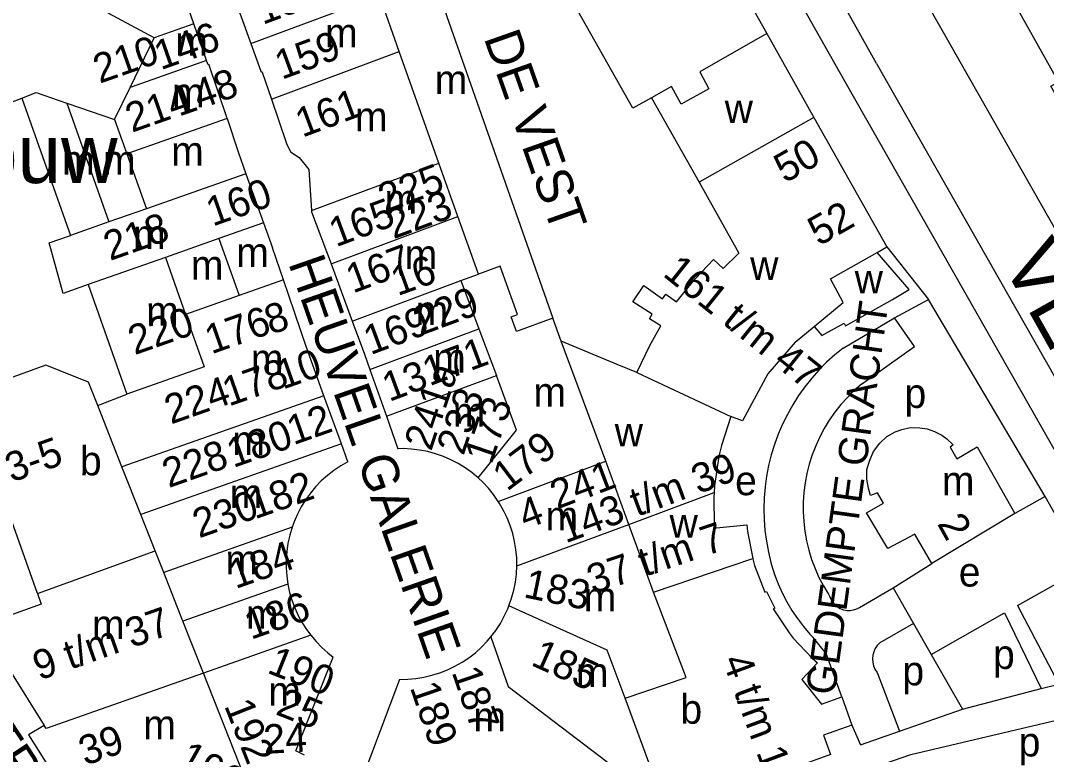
# Model space of a CAD drawing. Extents: x 160673 to 161924, y 382258 to 384145.
# Drawn here: x 161438.3 to 161578.5, y 383227.2 to 383327.4 of the extents above; entities that cross this region are included whole.
import ezdxf

# ---------------------------------------------------------------- set-up
doc = ezdxf.new("R2010")
doc.units = 0
for name, color, linetype in [('BLT_Basislijn', 7, 'Continuous'), ('BLT_Bebouwing', 7, 'Continuous'), ('BLT_Bebouwing_beschrifting', 7, 'Continuous'), ('BLT_Centroide', 7, 'Continuous'), ('BLT_Huisnummer', 7, 'Continuous'), ('BLT_Huisnummer_reeks', 7, 'Continuous'), ('BLT_Onderverdeling_panden', 7, 'Continuous'), ('BLT_Straatnaam', 7, 'Continuous'), ('BLT_Straatnaam_hoofdweg', 7, 'Continuous'), ('BLT_Straatnaam_verkleind', 7, 'Continuous'), ('BLT_Vlakafsluiter', 7, 'Continuous')]:
    doc.layers.add(name, color=color, linetype=linetype)

msp = doc.modelspace()

# ---------------------------------------------------------------- linework, layer by layer
at = {"layer": 'BLT_Basislijn'}
for p, q in [((161557.77, 383286.8), (161562.38, 383289.3)), ((161550.74, 383282.66), (161557.77, 383286.8)), ((161578.34, 383262.37), (161574.21, 383260.08)), ((161557.57, 383249.93), (161562.84, 383253.26)), ((161574.56, 383247.5), (161583.82, 383252.74)), ((161574.56, 383247.5), (161580.19, 383236.75)), ((161560.34, 383245.03), (161562.75, 383240.8)), ((161562.75, 383240.8), (161567.02, 383233.34)), ((161555.37, 383238.36), (161558.42, 383230.33)), ((161567.02, 383233.34), (161577.8, 383236.18)), ((161577.8, 383236.18), (161580.19, 383236.75))]:
    msp.add_line(p, q, dxfattribs=at)
for points in [[(161519.25, 383375.41), (161519.91, 383374.2), (161546.88, 383326.32), (161546.88, 383326.31)], [(161551.92, 383347.93), (161559.95, 383333.68), (161564.02, 383326.44), (161607.72, 383249.64), (161611.72, 383242.87)], [(161555.31, 383321.52), (161599.03, 383244.7), (161601.19, 383240.41)], [(161550.95, 383319.07), (161550.96, 383319.06), (161595.67, 383240.5)], [(161556.69, 383296.47), (161562.38, 383289.3)], [(161578.34, 383262.37), (161562.38, 383289.3)], [(161553.24, 383277.73), (161560.48, 383282.86), (161557.77, 383286.8)], [(161550.74, 383282.66), (161549.58, 383281.72), (161548.48, 383280.72), (161547.43, 383279.66), (161546.44, 383278.55), (161545.51, 383277.39), (161544.64, 383276.17), (161543.84, 383274.91), (161543.11, 383273.61), (161542.45, 383272.28), (161541.86, 383270.91), (161541.35, 383269.51), (161540.91, 383268.09), (161540.55, 383266.64), (161540.27, 383265.18), (161540.07, 383263.7), (161539.94, 383262.22), (161539.9, 383260.73), (161539.94, 383259.24), (161540.05, 383257.75), (161540.25, 383256.27), (161540.52, 383254.81), (161540.87, 383253.36), (161540.96, 383253.04)], [(161553.24, 383277.73), (161552.25, 383276.85), (161551.31, 383275.92), (161550.42, 383274.94), (161549.6, 383273.9), (161548.84, 383272.82), (161548.15, 383271.69), (161547.53, 383270.52), (161546.98, 383269.32), (161546.5, 383268.08), (161546.1, 383266.82), (161545.78, 383265.54), (161545.54, 383264.24), (161545.37, 383262.93), (161545.28, 383261.61), (161545.27, 383260.28), (161545.35, 383258.96), (161545.5, 383257.65), (161545.73, 383256.35), (161546.04, 383255.06), (161546.43, 383253.8), (161546.89, 383252.56), (161547.43, 383251.35), (161548.04, 383250.17), (161548.72, 383249.04), (161548.87, 383248.8)], [(161583.82, 383252.74), (161578.34, 383262.37)], [(161540.96, 383253.04), (161541.37, 383251.74), (161541.85, 383250.47), (161542.4, 383249.22), (161543.02, 383248.01), (161543.72, 383246.84), (161544.48, 383245.72), (161545.31, 383244.63), (161546.2, 383243.6), (161546.65, 383243.12)], [(161552.96, 383247.25), (161557.57, 383249.93)], [(161557.57, 383249.93), (161560.34, 383245.03)], [(161548.87, 383248.8), (161549.04, 383248.37), (161549.28, 383247.97), (161549.58, 383247.61), (161549.94, 383247.31), (161550.34, 383247.08), (161550.78, 383246.92), (161551.24, 383246.84), (161551.71, 383246.83), (161552.17, 383246.91), (161552.61, 383247.06), (161552.96, 383247.25)], [(161562.75, 383240.8), (161572.78, 383246.49), (161577.8, 383236.18)], [(161560.34, 383245.03), (161555.73, 383242.4)], [(161550.57, 383235.04), (161548.4, 383240.97), (161546.65, 383243.12)], [(161555.73, 383242.4), (161555.39, 383242.04), (161555.12, 383241.64), (161554.92, 383241.19), (161554.79, 383240.72), (161554.74, 383240.23), (161554.78, 383239.74), (161554.89, 383239.27), (161555.07, 383238.82), (161555.37, 383238.36)], [(161554.12, 383219.74), (161554.47, 383223.02), (161556.42, 383225.91), (161559.99, 383227.18), (161594.98, 383235.4), (161599.22, 383233.8)], [(161558.42, 383230.33), (161567.02, 383233.34)], [(161551.93, 383231.15), (161553.11, 383228.47), (161558.42, 383230.33)]]:
    msp.add_lwpolyline(points, dxfattribs=at)
at = {"layer": 'BLT_Bebouwing'}
for p, q in [((161525.54, 383351.86), (161540.29, 383325.62)), ((161492.41, 383339.91), (161511.06, 383286.74)), ((161512.21, 383283.62), (161511.06, 383286.74)), ((161535.4, 383273.33), (161534.11, 383269.35)), ((161534.11, 383269.35), (161533.74, 383267.89)), ((161533.74, 383267.89), (161533.17, 383263.84)), ((161533.17, 383263.84), (161533.12, 383262.92)), ((161533.12, 383262.92), (161533.08, 383262.26)), ((161533.08, 383262.26), (161533.1, 383258.59)), ((161553.94, 383260.15), (161556.23, 383261.47)), ((161533.1, 383258.59), (161533.13, 383258.12)), ((161550.57, 383235.04), (161551.93, 383231.15)), ((161551.93, 383231.15), (161551.93, 383231.15))]:
    msp.add_line(p, q, dxfattribs=at)
for points in [[(161524.55, 383316.85), (161521.98, 383315.42), (161509.32, 383337.88), (161507.85, 383337.05), (161503.92, 383344.05), (161492.41, 383339.91)], [(161585.65, 383310.6), (161582.67, 383315.9), (161581.09, 383315), (161579.13, 383318.43), (161580.16, 383319.01), (161566.25, 383343.82)], [(161540.29, 383325.62), (161546.74, 383314.17)], [(161524.55, 383316.85), (161531.04, 383305.33)], [(161546.74, 383314.17), (161556.69, 383296.47)], [(161531.04, 383305.33), (161536.46, 383295.62)], [(161555.39, 383295.73), (161556.69, 383296.47)], [(161522.55, 383279.34), (161524.31, 383283.02), (161525.82, 383285.68), (161524.26, 383286.65), (161524.65, 383287.29), (161522.01, 383288.98), (161523.49, 383291.2), (161526.06, 383289.4), (161526.5, 383290.01), (161527.98, 383288.96), (161530.54, 383292.18), (161533, 383294.74), (161534.32, 383293.51), (161536.46, 383295.62)], [(161546.78, 383285.61), (161547.83, 383284.39), (161550.88, 383286.08), (161551.06, 383285.69), (161557.47, 383289.3), (161559.77, 383290.67), (161555.39, 383295.73)], [(161544.2, 383283.47), (161546.78, 383285.61)], [(161522.55, 383279.34), (161519.88, 383280.44), (161512.21, 383283.62)], [(161544.2, 383283.47), (161540.45, 383279.15), (161536.96, 383272.72), (161535.4, 383273.33)], [(161440.66, 383249.13), (161435.92, 383262.48), (161433.78, 383268.46), (161422.18, 383264.37), (161418.91, 383263.22), (161417.75, 383266.43), (161415.63, 383272.29), (161414.36, 383271.79), (161410.57, 383277.81)], [(161556.23, 383261.47), (161555.42, 383262.9), (161554.49, 383262.53), (161554.19, 383263.53), (161553.98, 383264.76), (161553.98, 383266.09), (161554.36, 383267.37), (161554.88, 383268.56), (161555.73, 383269.67), (161556.71, 383270.57), (161557.82, 383271.21), (161558.76, 383271.55), (161559.91, 383271.8), (161561.19, 383271.76), (161562.21, 383271.63), (161563.23, 383271.25), (161564.21, 383270.78), (161564.9, 383270.27), (161565.76, 383269.44), (161565.35, 383269.11), (161566.26, 383267.53), (161569.03, 383269.16)], [(161569.03, 383269.16), (161574.21, 383260.08)], [(161562.84, 383253.26), (161560.53, 383257.26), (161556.85, 383255.27), (161553.94, 383260.15)], [(161574.21, 383260.08), (161562.84, 383253.26)], [(161533.13, 383258.12), (161533.45, 383258.13), (161537.57, 383258.54), (161537.67, 383257.61), (161538.38, 383253.94)], [(161538.38, 383253.94), (161538.39, 383253.9), (161538.64, 383252.99), (161540.03, 383249.32)], [(161440.66, 383249.13), (161441.17, 383247.71), (161434.9, 383245.47), (161432.99, 383244.79), (161441.57, 383231.12)], [(161540.03, 383249.32), (161540.25, 383249.42), (161541.41, 383247.16), (161541.18, 383247.03)], [(161541.18, 383247.03), (161543.35, 383243.79), (161543.91, 383243.03), (161546.52, 383240.3), (161547.22, 383239.68), (161545.1, 383237.38)], [(161545.1, 383237.38), (161547.76, 383234.01), (161550.57, 383235.04)], [(161441.57, 383231.12), (161439.44, 383229.84), (161444.39, 383221.97)], [(161551.93, 383231.15), (161548.05, 383229.78), (161549.02, 383227.14), (161544.14, 383225.4)]]:
    msp.add_lwpolyline(points, dxfattribs=at)
at = {"layer": 'BLT_Onderverdeling_panden'}
for p, q in [((161467.31, 383331.16), (161469.8, 383324.26)), ((161469.8, 383324.26), (161487.37, 383330.8)), ((161490.09, 383323.15), (161487.37, 383330.8)), ((161456.58, 383325.03), (161450.3, 383328.41)), ((161462.01, 383326.94), (161456.58, 383325.03)), ((161463.77, 383321.93), (161462.01, 383326.94)), ((161453.3, 383318.24), (161456.58, 383325.03)), ((161472.62, 383316.64), (161490.09, 383323.15)), ((161495.51, 383307.93), (161490.09, 383323.15)), ((161463.77, 383321.93), (161453.3, 383318.24)), ((161451.19, 383313.89), (161453.3, 383318.24)), ((161438.52, 383316.81), (161445.18, 383298.04)), ((161444.65, 383316.13), (161450.42, 383299.89)), ((161444.65, 383316.13), (161451.19, 383313.89)), ((161451.19, 383313.89), (161452.86, 383309.2)), ((161466.55, 383314.01), (161452.86, 383309.2)), ((161452.86, 383309.2), (161455.53, 383301.68)), ((161478.1, 383301.45), (161495.51, 383307.93)), ((161498.11, 383300.61), (161495.51, 383307.93)), ((161455.53, 383301.68), (161450.42, 383299.89)), ((161480.76, 383294.15), (161498.11, 383300.61)), ((161500, 383295.29), (161498.11, 383300.61)), ((161450.42, 383299.89), (161445.18, 383298.04)), ((161465.44, 383297.62), (161458.13, 383295.05)), ((161465.44, 383297.62), (161468.2, 383289.84)), ((161458.13, 383295.05), (161447.56, 383291.33)), ((161458.13, 383295.05), (161460.9, 383287.27)), ((161500.9, 383292.77), (161500, 383295.29)), ((161480.76, 383294.15), (161483.66, 383286.36)), ((161474.27, 383291.97), (161468.2, 383289.84)), ((161483.66, 383286.36), (161498.52, 383291.89)), ((161498.52, 383291.89), (161500.9, 383292.77)), ((161498.52, 383291.89), (161500.98, 383285.28)), ((161447.56, 383291.33), (161452.88, 383276.37)), ((161468.2, 383289.84), (161460.9, 383287.27)), ((161486.08, 383279.74), (161500.98, 383285.28)), ((161500.98, 383285.28), (161503.35, 383278.93)), ((161486.08, 383279.74), (161488.34, 383273.35)), ((161522.55, 383279.34), (161535.4, 383273.33)), ((161488.34, 383273.35), (161503.35, 383278.93)), ((161448.9, 383274.8), (161452.88, 383276.37)), ((161479.79, 383276.16), (161452.2, 383266.45)), ((161482.18, 383269.58), (161479.79, 383276.16)), ((161452.2, 383266.45), (161448.9, 383274.8)), ((161488.34, 383273.35), (161489.91, 383268.92)), ((161482.18, 383269.58), (161454.77, 383259.94)), ((161483.06, 383267.13), (161482.18, 383269.58)), ((161454.77, 383259.94), (161452.2, 383266.45)), ((161521.45, 383258.59), (161518.32, 383267.2)), ((161521.45, 383258.59), (161533.12, 383262.92)), ((161456.74, 383254.96), (161454.77, 383259.94)), ((161475.45, 383258.19), (161457.9, 383252.02)), ((161506.15, 383252.91), (161521.45, 383258.59)), ((161524.81, 383249.34), (161521.45, 383258.59)), ((161440.66, 383249.13), (161456.74, 383254.96)), ((161457.9, 383252.02), (161456.74, 383254.96)), ((161460.53, 383245.36), (161457.9, 383252.02)), ((161474.87, 383250.4), (161460.53, 383245.36)), ((161463.33, 383238.28), (161460.53, 383245.36)), ((161477.99, 383243.44), (161463.33, 383238.28)), ((161469.72, 383222.09), (161463.33, 383238.28)), ((161526.73, 383219.19), (161520.94, 383234.83))]:
    msp.add_line(p, q, dxfattribs=at)
for points in [[(161462.01, 383326.94), (161457.5, 383339.86), (161457.18, 383340.23), (161455.6, 383340.56)], [(161540.29, 383325.62), (161531.16, 383320.41), (161532.4, 383318.09), (161528.62, 383315.96), (161527.27, 383318.37), (161524.55, 383316.85)], [(161469.8, 383324.26), (161471.17, 383320.46), (161471.35, 383320.34), (161472.62, 383316.64)], [(161466.55, 383314.01), (161464.13, 383321.28), (161463.93, 383321.45), (161463.77, 383321.93)], [(161438.52, 383316.81), (161440.49, 383317.56), (161444.65, 383316.13)], [(161417.52, 383302.42), (161419.94, 383307.49), (161425.52, 383304.83), (161429.63, 383313.44), (161438.52, 383316.81)], [(161472.62, 383316.64), (161474.7, 383310.58), (161475.24, 383309.46), (161476.42, 383308.71), (161477.75, 383307.04), (161478.1, 383301.45)], [(161546.74, 383314.17), (161531.04, 383305.33)], [(161466.55, 383314.01), (161468.07, 383309.46), (161469.14, 383306.47)], [(161469.14, 383306.47), (161455.53, 383301.68)], [(161469.14, 383306.47), (161471.55, 383299.77)], [(161478.1, 383301.45), (161478.11, 383301.27), (161480.76, 383294.15)], [(161471.55, 383299.77), (161465.44, 383297.62)], [(161471.55, 383299.77), (161472.78, 383296.36)], [(161447.56, 383291.33), (161444.15, 383290.13), (161442.26, 383297.02), (161445.18, 383298.04)], [(161474.27, 383291.97), (161472.78, 383296.36)], [(161546.78, 383285.61), (161550.75, 383288.89), (161549.01, 383292.11), (161555.39, 383295.73)], [(161511.06, 383286.74), (161506.1, 383284.92), (161505.39, 383286.92), (161506.23, 383287.23), (161503.88, 383293.85), (161500.9, 383292.77)], [(161479.79, 383276.16), (161477.36, 383282.88), (161474.27, 383291.97)], [(161460.9, 383287.27), (161463.45, 383280.09), (161452.88, 383276.37)], [(161483.66, 383286.36), (161485.34, 383281.83), (161486.08, 383279.74)], [(161518.32, 383267.2), (161512.21, 383283.62)], [(161448.9, 383274.8), (161447.64, 383278.01), (161441.8, 383280.32), (161428.94, 383275.69), (161419.68, 383281.03)], [(161500.87, 383264.94), (161506.12, 383271.47), (161503.35, 383278.93)], [(161500.87, 383264.94), (161500.01, 383265.66), (161499.09, 383266.31), (161498.14, 383266.89), (161497.14, 383267.41), (161496.11, 383267.86), (161495.05, 383268.23), (161493.97, 383268.52), (161492.86, 383268.74), (161491.75, 383268.87), (161490.63, 383268.93), (161489.91, 383268.92)], [(161483.06, 383267.13), (161482.09, 383266.57), (161481.16, 383265.95), (161480.27, 383265.26), (161479.43, 383264.51), (161478.66, 383263.7), (161477.94, 383262.84), (161477.28, 383261.92), (161476.69, 383260.97), (161476.17, 383259.97), (161475.72, 383258.95), (161475.45, 383258.19)], [(161503.62, 383261.73), (161518.32, 383267.2)], [(161503.62, 383261.73), (161502.98, 383262.65), (161502.27, 383263.52), (161501.51, 383264.34), (161500.87, 383264.94)], [(161506.15, 383252.91), (161506.13, 383254.03), (161506.02, 383255.15), (161505.84, 383256.25), (161505.59, 383257.35), (161505.25, 383258.42), (161504.84, 383259.46), (161504.35, 383260.48), (161503.8, 383261.45), (161503.62, 383261.73)], [(161475.45, 383258.19), (161475.13, 383257.11), (161474.88, 383256.01), (161474.72, 383254.9), (161474.64, 383253.78), (161474.63, 383252.66), (161474.71, 383251.54), (161474.87, 383250.4)], [(161524.81, 383249.34), (161538.38, 383253.94)], [(161505.07, 383247.44), (161505.44, 383248.5), (161505.74, 383249.59), (161505.95, 383250.69), (161506.09, 383251.8), (161506.15, 383252.91)], [(161474.87, 383250.4), (161475.11, 383249.3), (161475.42, 383248.23), (161475.81, 383247.17), (161476.27, 383246.15), (161476.81, 383245.16), (161477.41, 383244.22), (161477.99, 383243.44)], [(161520.94, 383234.83), (161529.3, 383237.69), (161524.81, 383249.34)], [(161502.61, 383243.22), (161503.29, 383244.11), (161503.9, 383245.05), (161504.44, 383246.03), (161504.91, 383247.05), (161505.07, 383247.44)], [(161520.94, 383234.83), (161518.5, 383241.42), (161505.07, 383247.44)], [(161477.99, 383243.44), (161478.71, 383242.58), (161479.49, 383241.78), (161480.33, 383241.03), (161481.05, 383240.47)], [(161490.11, 383237.41), (161491.24, 383237.43), (161492.35, 383237.53), (161493.46, 383237.71), (161494.55, 383237.97), (161495.62, 383238.3), (161496.67, 383238.71), (161497.68, 383239.2), (161498.66, 383239.75), (161499.59, 383240.38), (161500.48, 383241.06), (161501.32, 383241.81), (161502.1, 383242.62), (161502.61, 383243.22)], [(161502.61, 383243.22), (161504.96, 383236.44), (161518.48, 383226.17), (161521.62, 383217.37)], [(161477.14, 383227.08), (161475.96, 383227.64), (161481.05, 383240.47)], [(161463.33, 383238.28), (161441.82, 383230.71), (161441.57, 383231.12)], [(161490.11, 383237.41), (161484.84, 383223.4), (161483.64, 383223.98)]]:
    msp.add_lwpolyline(points, dxfattribs=at)
at = {"layer": 'BLT_Vlakafsluiter'}
for p, q in [((161555.31, 383321.52), (161551.23, 383328.78)), ((161546.88, 383326.32), (161550.96, 383319.06))]:
    msp.add_line(p, q, dxfattribs=at)

# ---------------------------------------------------------------- texts
at = {"layer": 'BLT_Bebouwing_beschrifting'}
msp.add_text('Muziekgebouw', height=8, dxfattribs=at).set_placement((161380.24, 383305.2))
at = {"layer": 'BLT_Centroide'}
for s, p in [('m', (161479.95, 383323.72)), ('m', (161459.47, 383322.59)), ('m', (161494.93, 383317.34)), ('m', (161459.02, 383315.56)), ('w', (161534.55, 383313.4)), ('m', (161484.03, 383312.28)), ('m', (161458.92, 383307.57)), ('m', (161444.02, 383306.35)), ('m', (161449.61, 383306.35)), ('m', (161488.07, 383301.03)), ('m', (161453.72, 383296.19)), ('m', (161467.81, 383293.75)), ('m', (161490.82, 383293.47)), ('m', (161461.61, 383292.02)), ('w', (161538.03, 383291.98)), ('w', (161552.31, 383290.14)), ('m', (161455.5, 383285.72)), ('m', (161492.32, 383285.81)), ('m', (161469.81, 383279.22)), ('m', (161494.72, 383279.31)), ('m', (161508.42, 383274.66)), ('p', (161559.11, 383274.49)), ('m', (161497.4, 383271.94)), ('w', (161519.52, 383269.23)), ('m', (161467.28, 383268.06)), ('b', (161446.45, 383265.28)), ('e', (161535.97, 383262.57)), ('m', (161564.22, 383262.53)), ('m', (161466.91, 383260.81)), ('m', (161510.07, 383257.76)), ('w', (161527.02, 383256.78)), ('m', (161466.34, 383251.78)), ('e', (161566.53, 383250.09)), ('m', (161515.29, 383246.69)), ('m', (161469.13, 383244.34)), ('m', (161448.1, 383242.91)), ('p', (161571.21, 383238.84)), ('m', (161514.22, 383236.38)), ('p', (161558.82, 383236.6)), ('m', (161472.19, 383233.81)), ('b', (161528.5, 383231.37)), ('m', (161500.22, 383230.34)), ('m', (161455.11, 383229.25)), ('p', (161574.71, 383226.89))]:
    msp.add_text(s, height=4, dxfattribs=at).set_placement(p)
at = {"layer": 'BLT_Huisnummer'}
msp.add_text('2', height=4, rotation=299.117, dxfattribs=at).set_placement((161563.52, 383258.69))
at = {"layer": 'BLT_Huisnummer_reeks'}
for s, rotation, p in [('157', 20.4129, (161471.42, 383326.78)), ('146', 19.3836, (161457.48, 383320.59)), ('159', 20.4093, (161474.03, 383319.28)), ('210', 19.3854, (161449.14, 383318.75)), ('148', 19.3862, (161459.97, 383314.25)), ('214', 19.3862, (161453.55, 383312.06)), ('161', 20.4093, (161476.84, 383311.38)), ('50', 29.3582, (161542.76, 383305.11)), ('225', 20.4112, (161488.14, 383301.11)), ('160', 19.386, (161464.58, 383299.24)), ('165', 20.4112, (161481.43, 383296.41)), ('223', 20.4112, (161489.3, 383297.51)), ('52', 29.5983, (161547.41, 383296.52)), ('218', 19.3793, (161450.56, 383294.55)), ('167', 20.4102, (161483.74, 383290.1)), ('16', 19.8009, (161489.86, 383289.74)), ('161 t/m 47', 321.3254, (161525.95, 383292.61)), ('229', 20.4093, (161492.93, 383284.3)), ('8', 19.3866, (161472.54, 383284.45)), ('220', 19.3842, (161453.92, 383281.68)), ('176', 19.3866, (161464.41, 383281.79)), ('169', 20.4093, (161486.15, 383281.68)), ('171', 20.4115, (161494.2, 383277.43)), ('10', 19.3866, (161474.18, 383276.98)), ('178', 19.3866, (161466.8, 383274.66)), ('13', 20.4115, (161488.7, 383275.29)), ('241a', 71.2399, (161494.44, 383268.48)), ('224', 19.3866, (161458.89, 383272.21)), ('233', 71.2399, (161498.86, 383267.87)), ('12', 19.3869, (161475.62, 383269.38)), ('173', 71.2399, (161502.69, 383266.67)), ('180', 19.3869, (161467.4, 383266.27)), ('179', 37.1664, (161504.81, 383263.01)), ('3-5', 19.5226, (161437.12, 383264.28)), ('228', 19.3869, (161458.58, 383263.53)), ('143 t/m 39', 20.3752, (161512.8, 383255.97)), ('241', 20.6434, (161511.65, 383260.61)), ('182', 19.385, (161470.35, 383259.25)), ('230', 19.385, (161462.73, 383256.66)), ('4', 20.4128, (161507.31, 383257.88)), ('37 t/m 7', 18.7349, (161516.56, 383249.02)), ('184', 19.3875, (161467.7, 383249.73)), ('183', 348.4492, (161506.94, 383248.65)), ('186', 19.3864, (161469.82, 383242.8)), ('9 t/m 37', 19.387, (161440.9, 383237.24)), ('190', 338.2812, (161471.88, 383238.37)), ('185', 335.8273, (161507.92, 383239.42)), ('4 t/m 10', 290.309, (161534.18, 383240.03)), ('187', 288.9267, (161497.22, 383238.43)), ('25', 338.364, (161473.04, 383232.69)), ('189', 288.9267, (161491.51, 383236.34)), ('192', 291.5492, (161466.13, 383233.84)), ('24', 3.2654, (161471.63, 383227.23)), ('39', 19.3888, (161447.17, 383225.59)), ('196', 330.5687, (161459.56, 383225.72))]:
    msp.add_text(s, height=4, rotation=rotation, dxfattribs=at).set_placement(p)
at = {"layer": 'BLT_Straatnaam'}
for s, height, rotation, p in [('DE VEST', 5, 289.3989, (161501.59, 383325.05)), ('HEUVEL GALERIE', 4.9999, 289.2648, (161474.89, 383294.28)), ('JAN VAN LIESHOUTSTRAAT', 5, 303.3195, (161395.14, 383286.62))]:
    msp.add_text(s, height=height, rotation=rotation, dxfattribs=at).set_placement(p)
at = {"layer": 'BLT_Straatnaam_hoofdweg'}
msp.add_text('VESTDIJK', height=8, rotation=299.3368, dxfattribs=at).set_placement((161572.28, 383294.42))
at = {"layer": 'BLT_Straatnaam_verkleind'}
msp.add_text('GEDEMPTE GRACHT', height=4, rotation=82.2008, dxfattribs=at).set_placement((161549.58, 383235.14))

doc.saveas('drawing.dxf')
